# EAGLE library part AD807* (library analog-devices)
500 MHz, G = +1 and +2 Triple Video Buffers with Disable Source: http://www.analog.com/static/imported-files/data_sheets/AD8074_8075.pdf
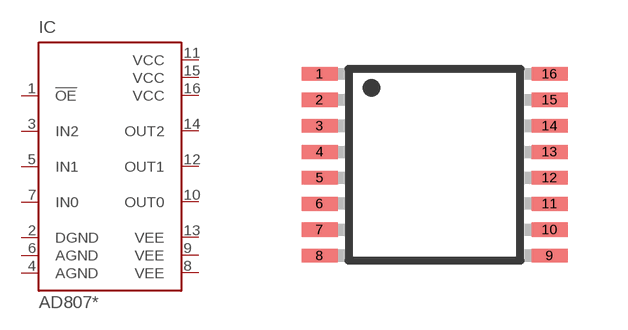
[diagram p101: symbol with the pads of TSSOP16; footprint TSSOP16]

Designator prefix IC

## AD8074RU (MPN: AD8074ARUZ; OC_FARNELL: 9426027; OC_NEWARK: 19M0929), AD8075RU (MPN: AD8075ARUZ; OC_FARNELL: 9426035; OC_NEWARK: 19M0930)  [TSSOP16]
1  !OE  in
2  DGND  in
3  IN2  in
4  AGND  in
5  IN1  in
6  AGND  in
7  IN0  in
8  VEE  in
9  VEE  in
10  OUT0  hiz
11  VCC  in
12  OUT1  hiz
13  VEE  in
14  OUT2  hiz
15  VCC  in
16  VCC  in

## Footprint TSSOP16 (pad centres in mm)
16-Lead Thin Shrink Small Outline Package [TSSOP] (RU-16) Source: 8x ADG1408_1409.pdf
smd 0.9 x 0.35: 1 -2.875,2.275; 2 -2.875,1.625; 3 -2.875,0.975; 4 -2.875,0.325; 5 -2.875,-0.325; 6 -2.875,-0.975; 7 -2.875,-1.625; 8 -2.875,-2.275; 9 2.875,-2.275; 10 2.875,-1.625; 11 2.875,-0.975; 12 2.875,-0.325; 13 2.875,0.325; 14 2.875,0.975; 15 2.875,1.625; 16 2.875,2.275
